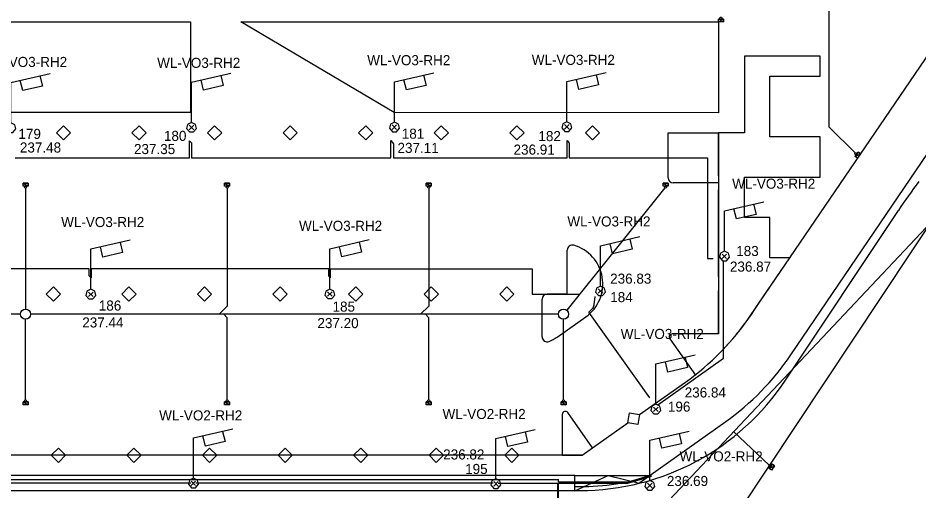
# Model space of a CAD drawing. Extents: x -264222 to -263592, y -1242345 to -1242048.
# Drawn here: x -263871.6 to -263782.2, y -1242301.5 to -1242254.6 of the extents above; entities that cross this region are included whole.
import ezdxf

# ---------------------------------------------------------------- set-up
doc = ezdxf.new("R2010")
doc.units = 0
for name, color, linetype in [('BOD_CISLO', 7, 'Continuous'), ('BOD_SYMBOL', 7, 'Continuous'), ('BOD_VYSKA', 7, 'Continuous'), ('KFA_2D_SITUACIA_DSP', 7, 'Continuous'), ('KFA_SO_62-1_VO_LAMPY_MERANE', 7, 'Continuous'), ('KFA_SO_62-1_VO_POPIS_LAMP_PROJEKT', 7, 'Continuous'), ('KFA_SO_62-1_VO_TRASA_KABLOV_PROJEKT', 7, 'Continuous')]:
    doc.layers.add(name, color=color, linetype=linetype)

msp = doc.modelspace()

# ---------------------------------------------------------------- linework, layer by layer
at = {"layer": 'BOD_SYMBOL'}
for p, q in [((-263817.336, -1242265.613), (-263816.894, -1242265.171)), ((-263816.894, -1242265.613), (-263817.336, -1242265.171)), ((-263854.587, -1242265.676), (-263854.145, -1242265.234)), ((-263854.145, -1242265.676), (-263854.587, -1242265.234)), ((-263834.447, -1242265.648), (-263834.005, -1242265.206)), ((-263834.005, -1242265.648), (-263834.447, -1242265.206)), ((-263801.697, -1242278.454), (-263801.255, -1242278.012)), ((-263801.255, -1242278.454), (-263801.697, -1242278.012)), ((-263864.574, -1242282.234), (-263864.132, -1242281.792)), ((-263864.132, -1242282.234), (-263864.574, -1242281.792)), ((-263840.849, -1242282.207), (-263840.407, -1242281.765)), ((-263840.407, -1242282.207), (-263840.849, -1242281.765)), ((-263813.995, -1242281.912), (-263813.553, -1242281.47)), ((-263813.553, -1242281.912), (-263813.995, -1242281.47)), ((-263808.507, -1242293.645), (-263808.065, -1242293.203)), ((-263808.065, -1242293.645), (-263808.507, -1242293.203)), ((-263854.391, -1242300.987), (-263853.949, -1242300.545)), ((-263853.949, -1242300.987), (-263854.391, -1242300.545)), ((-263824.373, -1242301.038), (-263823.931, -1242300.596)), ((-263823.931, -1242301.038), (-263824.373, -1242300.596)), ((-263809.101, -1242301.204), (-263808.659, -1242300.762)), ((-263808.659, -1242301.204), (-263809.101, -1242300.762))]:
    msp.add_line(p, q, dxfattribs=at)
at = {"layer": 'KFA_2D_SITUACIA_DSP'}
for p, q in [((-263822.88, -1242337.914), (-263734.49, -1242204.937)), ((-263794.898, -1242288.032), (-263742.736, -1242211.145)), ((-263798.899, -1242284.125), (-263751.864, -1242215.081)), ((-263791.063, -1242265.427), (-263791.063, -1242253.362)), ((-263802.071, -1242254.697), (-263801.571, -1242254.697)), ((-263802.071, -1242254.987), (-263802.071, -1242254.697)), ((-263802.071, -1242254.697), (-263801.571, -1242254.987)), ((-263802.071, -1242254.697), (-263801.571, -1242254.987)), ((-263801.571, -1242254.697), (-263802.071, -1242254.697)), ((-263801.571, -1242254.987), (-263802.071, -1242254.987)), ((-263801.571, -1242254.697), (-263801.571, -1242254.987)), ((-263801.571, -1242254.987), (-263801.571, -1242254.697)), ((-263807.068, -1242270.447), (-263807.068, -1242265.987)), ((-263807.068, -1242265.987), (-263802.068, -1242265.987)), ((-263802.068, -1242270.24), (-263802.068, -1242265.987)), ((-263788.502, -1242267.989), (-263791.063, -1242265.427)), ((-263788.491, -1242268.322), (-263788.207, -1242267.91)), ((-263788.207, -1242267.91), (-263788.491, -1242268.322)), ((-263788.491, -1242268.322), (-263787.968, -1242268.075)), ((-263788.491, -1242268.322), (-263787.968, -1242268.075)), ((-263788.252, -1242268.487), (-263788.491, -1242268.322)), ((-263787.968, -1242268.075), (-263788.252, -1242268.487)), ((-263788.207, -1242267.91), (-263787.968, -1242268.075)), ((-263787.968, -1242268.075), (-263788.207, -1242267.91)), ((-263871.074, -1242270.983), (-263870.574, -1242270.983)), ((-263871.074, -1242271.273), (-263871.074, -1242270.983)), ((-263871.074, -1242270.983), (-263870.574, -1242271.273)), ((-263871.074, -1242270.983), (-263870.574, -1242271.273)), ((-263870.574, -1242270.983), (-263871.074, -1242270.983)), ((-263870.574, -1242271.273), (-263871.074, -1242271.273)), ((-263870.574, -1242270.983), (-263870.574, -1242271.273)), ((-263870.574, -1242271.273), (-263870.574, -1242270.983)), ((-263851.074, -1242270.983), (-263850.574, -1242270.983)), ((-263851.074, -1242271.273), (-263851.074, -1242270.983)), ((-263851.074, -1242270.983), (-263850.574, -1242271.273)), ((-263851.074, -1242270.983), (-263850.574, -1242271.273)), ((-263850.574, -1242270.983), (-263851.074, -1242270.983)), ((-263850.574, -1242271.273), (-263851.074, -1242271.273)), ((-263850.574, -1242270.983), (-263850.574, -1242271.273)), ((-263850.574, -1242271.273), (-263850.574, -1242270.983)), ((-263831.074, -1242270.983), (-263830.574, -1242270.983)), ((-263831.074, -1242271.273), (-263831.074, -1242270.983)), ((-263831.074, -1242270.983), (-263830.574, -1242271.273)), ((-263831.074, -1242270.983), (-263830.574, -1242271.273)), ((-263830.574, -1242270.983), (-263831.074, -1242270.983)), ((-263830.574, -1242271.273), (-263831.074, -1242271.273)), ((-263830.574, -1242270.983), (-263830.574, -1242271.273)), ((-263830.574, -1242271.273), (-263830.574, -1242270.983)), ((-263807.568, -1242270.982), (-263807.068, -1242270.982)), ((-263807.568, -1242271.272), (-263807.568, -1242270.982)), ((-263807.568, -1242270.982), (-263807.068, -1242271.272)), ((-263807.568, -1242270.982), (-263807.068, -1242271.272)), ((-263807.068, -1242270.982), (-263807.568, -1242270.982)), ((-263807.068, -1242271.272), (-263807.568, -1242271.272)), ((-263807.068, -1242270.982), (-263807.068, -1242271.272)), ((-263807.068, -1242271.272), (-263807.068, -1242270.982)), ((-263802.068, -1242270.947), (-263806.568, -1242270.947)), ((-263870.824, -1242271.473), (-263870.824, -1242283.482)), ((-263850.824, -1242271.473), (-263850.824, -1242283.187)), ((-263830.824, -1242271.473), (-263830.824, -1242283.187)), ((-263807.38, -1242271.45), (-263817.128, -1242283.593)), ((-263802.068, -1242280.24), (-263802.068, -1242271.654)), ((-263795.416, -1242290.541), (-263784.214, -1242273.68)), ((-263780.353, -1242274.236), (-263808.248, -1242303.783)), ((-263817.068, -1242281.982), (-263817.068, -1242277.62)), ((-263817.068, -1242281.982), (-263819.068, -1242281.982)), ((-263802.068, -1242285.947), (-263802.068, -1242281.654)), ((-263819.568, -1242286.231), (-263819.568, -1242282.482)), ((-263850.824, -1242283.187), (-263851.619, -1242283.982)), ((-263830.824, -1242283.187), (-263831.619, -1242283.982)), ((-263871.324, -1242283.982), (-263903.413, -1242283.982)), ((-263870.824, -1242292.492), (-263870.824, -1242284.482)), ((-263817.941, -1242283.982), (-263870.324, -1242283.982)), ((-263817.941, -1242283.982), (-263870.324, -1242283.982)), ((-263850.824, -1242284.343), (-263851.149, -1242283.982)), ((-263850.824, -1242292.492), (-263850.824, -1242284.343)), ((-263830.824, -1242284.343), (-263831.149, -1242283.982)), ((-263830.824, -1242292.492), (-263830.824, -1242284.343)), ((-263818.06, -1242286.248), (-263815.232, -1242284.248)), ((-263817.441, -1242292.492), (-263817.441, -1242284.482)), ((-263809.895, -1242293.947), (-263805.344, -1242290.728)), ((-263871.074, -1242292.693), (-263870.574, -1242292.693)), ((-263871.074, -1242292.983), (-263871.074, -1242292.693)), ((-263871.074, -1242292.693), (-263870.574, -1242292.983)), ((-263871.074, -1242292.693), (-263870.574, -1242292.983)), ((-263870.574, -1242292.693), (-263871.074, -1242292.693)), ((-263870.574, -1242292.693), (-263870.574, -1242292.983)), ((-263870.574, -1242292.983), (-263870.574, -1242292.693)), ((-263851.074, -1242292.693), (-263850.574, -1242292.693)), ((-263851.074, -1242292.983), (-263851.074, -1242292.693)), ((-263851.074, -1242292.693), (-263850.574, -1242292.983)), ((-263851.074, -1242292.693), (-263850.574, -1242292.983)), ((-263850.574, -1242292.693), (-263851.074, -1242292.693)), ((-263850.574, -1242292.693), (-263850.574, -1242292.983)), ((-263850.574, -1242292.983), (-263850.574, -1242292.693)), ((-263831.074, -1242292.693), (-263830.574, -1242292.693)), ((-263831.074, -1242292.983), (-263831.074, -1242292.693)), ((-263831.074, -1242292.693), (-263830.574, -1242292.983)), ((-263831.074, -1242292.693), (-263830.574, -1242292.983)), ((-263830.574, -1242292.693), (-263831.074, -1242292.693)), ((-263830.824, -1242292.693), (-263830.824, -1242292.692)), ((-263830.574, -1242292.693), (-263830.574, -1242292.983)), ((-263830.574, -1242292.983), (-263830.574, -1242292.693)), ((-263817.691, -1242292.692), (-263817.191, -1242292.692)), ((-263817.691, -1242292.982), (-263817.691, -1242292.692)), ((-263817.691, -1242292.692), (-263817.191, -1242292.982)), ((-263817.691, -1242292.692), (-263817.191, -1242292.982)), ((-263817.191, -1242292.692), (-263817.691, -1242292.692)), ((-263817.191, -1242292.692), (-263817.191, -1242292.982)), ((-263817.191, -1242292.982), (-263817.191, -1242292.692)), ((-263870.574, -1242292.983), (-263871.074, -1242292.983)), ((-263850.574, -1242292.983), (-263851.074, -1242292.983)), ((-263830.574, -1242292.983), (-263831.074, -1242292.983)), ((-263817.191, -1242292.982), (-263817.691, -1242292.982)), ((-263809.875, -1242300.669), (-263801.342, -1242294.634)), ((-263814.555, -1242297.242), (-263811.05, -1242294.763)), ((-263797.048, -1242298.952), (-263800.558, -1242295.638)), ((-263815.601, -1242297.982), (-263917.08, -1242297.982)), ((-263797.029, -1242299.286), (-263796.75, -1242298.871)), ((-263796.75, -1242298.871), (-263797.029, -1242299.286)), ((-263797.029, -1242299.286), (-263796.51, -1242299.032)), ((-263797.029, -1242299.286), (-263796.51, -1242299.032)), ((-263796.51, -1242299.032), (-263796.788, -1242299.448)), ((-263796.75, -1242298.871), (-263796.51, -1242299.032)), ((-263796.51, -1242299.032), (-263796.75, -1242298.871)), ((-263816.308, -1242299.982), (-263918.049, -1242299.982)), ((-263816.308, -1242301.482), (-263816.308, -1242299.982)), ((-263816.308, -1242299.982), (-263808.904, -1242299.982)), ((-263796.788, -1242299.448), (-263797.029, -1242299.286)), ((-263809.906, -1242300.757), (-263809.875, -1242300.669)), ((-263914.08, -1242301.482), (-263815.822, -1242301.482))]:
    msp.add_line(p, q, dxfattribs=at)
for points in [[(-263854.468, -1242263.985), (-263917.08, -1242263.982), (-263901.868, -1242254.982), (-263854.468, -1242254.985), (-263854.468, -1242263.985)], [(-263798.064, -1242282.882), (-263794.987, -1242278.383), (-263796.968, -1242278.382), (-263796.968, -1242274.382), (-263799.468, -1242274.382), (-263799.468, -1242270.382), (-263791.968, -1242270.382), (-263791.968, -1242266.382), (-263796.968, -1242266.382), (-263796.968, -1242260.382), (-263791.968, -1242260.382), (-263791.968, -1242258.382), (-263799.468, -1242258.382), (-263799.468, -1242265.987), (-263802.068, -1242265.987)], [(-263802.068, -1242265.987), (-263802.068, -1242270.24), (-263802.068, -1242270.947), (-263802.068, -1242271.654), (-263802.068, -1242273.447), (-263802.068, -1242275.947), (-263802.068, -1242278.447), (-263802.068, -1242280.24), (-263802.068, -1242280.24), (-263802.068, -1242281.654), (-263802.068, -1242283.447), (-263802.068, -1242285.947), (-263806.656, -1242285.943)], [(-263806.901, -1242286.416), (-263804.349, -1242290.024), (-263802.552, -1242288.44)], [(-263817.568, -1242293.926), (-263817.568, -1242297.982), (-263815.601, -1242297.982), (-263814.555, -1242297.242), (-263817.023, -1242293.753)], [(-263816.327, -1242301.51), (-263813.002, -1242299.982), (-263809.906, -1242300.757)]]:
    msp.add_lwpolyline(points, dxfattribs=at)
for points in [[(-263802.068, -1242263.988), (-263834.256, -1242263.984), (-263849.468, -1242254.985), (-263802.068, -1242254.987)], [(-263867.068, -1242265.279), (-263866.361, -1242265.986), (-263867.068, -1242266.693), (-263867.775, -1242265.986)], [(-263859.568, -1242265.279), (-263858.861, -1242265.986), (-263859.568, -1242266.693), (-263860.275, -1242265.986)], [(-263852.068, -1242265.279), (-263851.361, -1242265.986), (-263852.068, -1242266.693), (-263852.775, -1242265.986)], [(-263844.568, -1242265.279), (-263843.861, -1242265.986), (-263844.568, -1242266.693), (-263845.275, -1242265.986)], [(-263837.068, -1242265.279), (-263836.361, -1242265.986), (-263837.068, -1242266.693), (-263837.775, -1242265.986)], [(-263829.568, -1242265.279), (-263828.861, -1242265.986), (-263829.568, -1242266.693), (-263830.275, -1242265.986)], [(-263822.068, -1242265.279), (-263821.361, -1242265.986), (-263822.068, -1242266.694), (-263822.775, -1242265.986)], [(-263814.568, -1242265.279), (-263813.861, -1242265.986), (-263814.568, -1242266.693), (-263815.275, -1242265.986)], [(-263868.068, -1242281.275), (-263867.361, -1242281.982), (-263868.068, -1242282.689), (-263868.775, -1242281.982)], [(-263860.568, -1242281.275), (-263859.861, -1242281.982), (-263860.568, -1242282.689), (-263861.275, -1242281.982)], [(-263853.068, -1242281.275), (-263852.361, -1242281.982), (-263853.068, -1242282.689), (-263853.775, -1242281.982)], [(-263845.568, -1242281.275), (-263844.861, -1242281.982), (-263845.568, -1242282.689), (-263846.275, -1242281.982)], [(-263838.068, -1242281.275), (-263837.361, -1242281.982), (-263838.068, -1242282.689), (-263838.775, -1242281.982)], [(-263830.568, -1242281.275), (-263829.861, -1242281.982), (-263830.568, -1242282.689), (-263831.275, -1242281.982)], [(-263823.068, -1242281.275), (-263822.361, -1242281.982), (-263823.068, -1242282.689), (-263823.775, -1242281.982)], [(-263810.881, -1242293.778), (-263809.895, -1242293.947), (-263810.064, -1242294.932), (-263811.05, -1242294.763)], [(-263867.568, -1242297.275), (-263866.861, -1242297.982), (-263867.568, -1242298.689), (-263868.275, -1242297.982)], [(-263860.068, -1242297.275), (-263859.361, -1242297.982), (-263860.068, -1242298.689), (-263860.775, -1242297.982)], [(-263852.568, -1242297.275), (-263851.861, -1242297.982), (-263852.568, -1242298.689), (-263853.275, -1242297.982)], [(-263845.068, -1242297.275), (-263844.361, -1242297.982), (-263845.068, -1242298.689), (-263845.775, -1242297.982)], [(-263837.568, -1242297.275), (-263836.861, -1242297.982), (-263837.568, -1242298.689), (-263838.275, -1242297.982)], [(-263830.068, -1242297.275), (-263829.361, -1242297.982), (-263830.068, -1242298.689), (-263830.775, -1242297.982)], [(-263822.568, -1242297.275), (-263821.861, -1242297.982), (-263822.568, -1242298.689), (-263823.275, -1242297.982)]]:
    msp.add_lwpolyline(points, close=True, dxfattribs=at)
for centre, radius in [((-263801.821, -1242254.597), 0.1), ((-263788.431, -1242268.059), 0.1), ((-263870.824, -1242271.373), 0.1), ((-263850.824, -1242271.373), 0.1), ((-263830.824, -1242271.373), 0.1), ((-263807.318, -1242271.372), 0.1), ((-263870.824, -1242283.982), 0.5), ((-263817.441, -1242283.982), 0.5), ((-263870.824, -1242292.592), 0.1), ((-263850.824, -1242292.592), 0.1), ((-263830.824, -1242292.592), 0.1), ((-263817.441, -1242292.592), 0.1), ((-263796.975, -1242299.02), 0.1)]:
    msp.add_circle(centre, radius, dxfattribs=at)
for centre, radius, start, end in [((-263806.568, -1242270.447), 0.5, 180, 270), ((-263742.568, -1242301.35), 50, 142.36875, 146.39918), ((-263816.568, -1242277.62), 0.5, 73.84458, 180), ((-263817.542, -1242280.982), 4, 305.27024, 73.84458), ((-263819.068, -1242282.482), 0.5, 90, 180), ((-263821.806, -1242268.304), 27.86, 313.71918, 328.45017), ((-263820.069, -1242269.909), 25.5, 305.27024, 326.11647), ((-263819.068, -1242286.231), 0.5, 180, 291.83316), ((-263820.369, -1242282.982), 4, 291.83316, 305.27024), ((-263806.656, -1242286.243), 0.3, 89.94357, 215.27024), ((-263816.067, -1242273.815), 25.5, 305.27024, 326.11647), ((-263815.822, -1242276.982), 24.5, 270, 326.39918), ((-263817.268, -1242293.926), 0.3, 35.27024, 180), ((-263815.836, -1242276.967), 24.119, 268.87866, 286.17976)]:
    msp.add_arc(centre, radius, start, end, dxfattribs=at)
at = {"layer": 'KFA_SO_62-1_VO_LAMPY_MERANE'}
for p, q in [((-263854.416, -1242265.455), (-263854.316, -1242265.455)), ((-263854.366, -1242265.455), (-263854.366, -1242265.455)), ((-263834.276, -1242265.427), (-263834.176, -1242265.427)), ((-263834.226, -1242265.427), (-263834.226, -1242265.427)), ((-263817.165, -1242265.392), (-263817.065, -1242265.392)), ((-263817.115, -1242265.392), (-263817.115, -1242265.392)), ((-263801.526, -1242278.233), (-263801.426, -1242278.233)), ((-263801.476, -1242278.233), (-263801.476, -1242278.233)), ((-263864.403, -1242282.013), (-263864.303, -1242282.013)), ((-263864.353, -1242282.013), (-263864.353, -1242282.013)), ((-263840.678, -1242281.986), (-263840.578, -1242281.986)), ((-263840.628, -1242281.986), (-263840.628, -1242281.986)), ((-263813.824, -1242281.691), (-263813.724, -1242281.691)), ((-263813.774, -1242281.691), (-263813.774, -1242281.691)), ((-263808.336, -1242293.424), (-263808.236, -1242293.424)), ((-263808.286, -1242293.424), (-263808.286, -1242293.424)), ((-263854.22, -1242300.766), (-263854.12, -1242300.766)), ((-263854.17, -1242300.766), (-263854.17, -1242300.766)), ((-263824.202, -1242300.817), (-263824.102, -1242300.817)), ((-263824.152, -1242300.817), (-263824.152, -1242300.817)), ((-263808.93, -1242300.983), (-263808.83, -1242300.983)), ((-263808.88, -1242300.983), (-263808.88, -1242300.983))]:
    msp.add_line(p, q, dxfattribs=at)
for points in [[(-263872.3, -1242264.999), (-263872.7, -1242265.199), (-263872.8, -1242265.599), (-263872.5, -1242265.949), (-263872.1, -1242265.949), (-263871.8, -1242265.599), (-263871.9, -1242265.199), (-263872.3, -1242264.999), (-263872.3, -1242260.999), (-263868.4, -1242260.099)], [(-263869.4, -1242260.349), (-263869.15, -1242261.349), (-263871.1, -1242261.799), (-263871.35, -1242260.799)], [(-263854.366, -1242264.955), (-263854.766, -1242265.155), (-263854.866, -1242265.555), (-263854.566, -1242265.905), (-263854.166, -1242265.905), (-263853.866, -1242265.555), (-263853.966, -1242265.155), (-263854.366, -1242264.955), (-263854.366, -1242260.955), (-263850.466, -1242260.055)], [(-263851.466, -1242260.305), (-263851.216, -1242261.305), (-263853.166, -1242261.755), (-263853.416, -1242260.755)], [(-263834.226, -1242264.927), (-263834.626, -1242265.127), (-263834.726, -1242265.527), (-263834.426, -1242265.877), (-263834.026, -1242265.877), (-263833.726, -1242265.527), (-263833.826, -1242265.127), (-263834.226, -1242264.927), (-263834.226, -1242260.927), (-263830.326, -1242260.027)], [(-263831.326, -1242260.277), (-263831.076, -1242261.277), (-263833.026, -1242261.727), (-263833.276, -1242260.727)], [(-263817.115, -1242264.892), (-263817.515, -1242265.092), (-263817.615, -1242265.492), (-263817.315, -1242265.842), (-263816.915, -1242265.842), (-263816.615, -1242265.492), (-263816.715, -1242265.092), (-263817.115, -1242264.892), (-263817.115, -1242260.892), (-263813.215, -1242259.992)], [(-263814.215, -1242260.242), (-263813.965, -1242261.242), (-263815.915, -1242261.692), (-263816.165, -1242260.692)], [(-263801.476, -1242277.733), (-263801.876, -1242277.933), (-263801.976, -1242278.333), (-263801.676, -1242278.683), (-263801.276, -1242278.683), (-263800.976, -1242278.333), (-263801.076, -1242277.933), (-263801.476, -1242277.733), (-263801.476, -1242273.733), (-263797.576, -1242272.833)], [(-263798.576, -1242273.083), (-263798.326, -1242274.083), (-263800.276, -1242274.533), (-263800.526, -1242273.533)], [(-263864.353, -1242281.513), (-263864.753, -1242281.713), (-263864.853, -1242282.113), (-263864.553, -1242282.463), (-263864.153, -1242282.463), (-263863.853, -1242282.113), (-263863.953, -1242281.713), (-263864.353, -1242281.513), (-263864.353, -1242277.513), (-263860.453, -1242276.613)], [(-263840.628, -1242281.486), (-263841.028, -1242281.686), (-263841.128, -1242282.086), (-263840.828, -1242282.436), (-263840.428, -1242282.436), (-263840.128, -1242282.086), (-263840.228, -1242281.686), (-263840.628, -1242281.486), (-263840.628, -1242277.486), (-263836.728, -1242276.586)], [(-263813.774, -1242281.191), (-263814.174, -1242281.391), (-263814.274, -1242281.791), (-263813.974, -1242282.141), (-263813.574, -1242282.141), (-263813.274, -1242281.791), (-263813.374, -1242281.391), (-263813.774, -1242281.191), (-263813.774, -1242277.191), (-263809.874, -1242276.291)], [(-263810.874, -1242276.541), (-263810.624, -1242277.541), (-263812.574, -1242277.991), (-263812.824, -1242276.991)], [(-263861.453, -1242276.863), (-263861.203, -1242277.863), (-263863.153, -1242278.313), (-263863.403, -1242277.313)], [(-263837.728, -1242276.836), (-263837.478, -1242277.836), (-263839.428, -1242278.286), (-263839.678, -1242277.286)], [(-263808.286, -1242292.924), (-263808.686, -1242293.124), (-263808.786, -1242293.524), (-263808.486, -1242293.874), (-263808.086, -1242293.874), (-263807.786, -1242293.524), (-263807.886, -1242293.124), (-263808.286, -1242292.924), (-263808.286, -1242288.924), (-263804.386, -1242288.024)], [(-263805.386, -1242288.274), (-263805.136, -1242289.274), (-263807.086, -1242289.724), (-263807.336, -1242288.724)], [(-263854.17, -1242300.266), (-263854.57, -1242300.466), (-263854.67, -1242300.866), (-263854.37, -1242301.216), (-263853.97, -1242301.216), (-263853.67, -1242300.866), (-263853.77, -1242300.466), (-263854.17, -1242300.266), (-263854.17, -1242296.266), (-263850.27, -1242295.366)], [(-263824.152, -1242300.317), (-263824.552, -1242300.517), (-263824.652, -1242300.917), (-263824.352, -1242301.267), (-263823.952, -1242301.267), (-263823.652, -1242300.917), (-263823.752, -1242300.517), (-263824.152, -1242300.317), (-263824.152, -1242296.317), (-263820.252, -1242295.417)], [(-263808.88, -1242300.483), (-263809.28, -1242300.683), (-263809.38, -1242301.083), (-263809.08, -1242301.433), (-263808.68, -1242301.433), (-263808.38, -1242301.083), (-263808.48, -1242300.683), (-263808.88, -1242300.483), (-263808.88, -1242296.483), (-263804.98, -1242295.583)], [(-263851.27, -1242295.616), (-263851.02, -1242296.616), (-263852.97, -1242297.066), (-263853.22, -1242296.066)], [(-263821.252, -1242295.667), (-263821.002, -1242296.667), (-263822.952, -1242297.117), (-263823.202, -1242296.117)], [(-263805.98, -1242295.833), (-263805.73, -1242296.833), (-263807.68, -1242297.283), (-263807.93, -1242296.283)]]:
    msp.add_lwpolyline(points, dxfattribs=at)
at = {"layer": 'KFA_SO_62-1_VO_TRASA_KABLOV_PROJEKT'}
for p, q in [((-263854.568, -1242268.463), (-263854.568, -1242266.768)), ((-263854.568, -1242266.768), (-263854.357, -1242266.976)), ((-263854.357, -1242266.976), (-263854.357, -1242268.463)), ((-263834.568, -1242268.463), (-263834.568, -1242266.764)), ((-263834.568, -1242266.764), (-263834.32, -1242267.08)), ((-263817.068, -1242268.463), (-263817.068, -1242266.765)), ((-263817.068, -1242266.765), (-263816.865, -1242267.008)), ((-263834.32, -1242267.08), (-263834.32, -1242268.463)), ((-263816.865, -1242267.008), (-263816.865, -1242268.463)), ((-263871.858, -1242268.463), (-263854.568, -1242268.463)), ((-263854.357, -1242268.463), (-263834.568, -1242268.463)), ((-263834.32, -1242268.463), (-263817.068, -1242268.463)), ((-263816.865, -1242268.463), (-263803.15, -1242268.463)), ((-263803.15, -1242268.463), (-263803.15, -1242278.447)), ((-263803.15, -1242278.447), (-263802.589, -1242278.447)), ((-263864.522, -1242279.482), (-263888.068, -1242279.482)), ((-263864.522, -1242280.178), (-263864.522, -1242279.482)), ((-263840.736, -1242279.482), (-263864.31, -1242279.482)), ((-263864.31, -1242279.482), (-263864.31, -1242280.377)), ((-263840.736, -1242280.216), (-263840.736, -1242279.482)), ((-263840.571, -1242280.373), (-263840.571, -1242279.482)), ((-263840.571, -1242279.482), (-263820.568, -1242279.482)), ((-263820.568, -1242279.482), (-263820.568, -1242281.982)), ((-263801.558, -1242288.362), (-263801.558, -1242278.697)), ((-263864.31, -1242280.377), (-263864.522, -1242280.178)), ((-263840.571, -1242280.373), (-263840.736, -1242280.216)), ((-263820.568, -1242281.982), (-263815.925, -1242281.982)), ((-263814.51, -1242283.35), (-263814.4, -1242283.05)), ((-263814.4, -1242283.05), (-263814.313, -1242282.232)), ((-263814.94, -1242283.77), (-263814.71, -1242283.56)), ((-263808.865, -1242292.299), (-263814.94, -1242283.77)), ((-263814.71, -1242283.56), (-263814.51, -1242283.35)), ((-263808.08, -1242292.976), (-263801.558, -1242288.362)), ((-263811.045, -1242300.75), (-263808.72, -1242300.04)), ((-263808.896, -1242300.019), (-263811.043, -1242300.664)), ((-263808.72, -1242300.04), (-263808.896, -1242300.019)), ((-263918.795, -1242300.4), (-263817.945, -1242300.4)), ((-263854.424, -1242300.744), (-263883.924, -1242300.744)), ((-263824.424, -1242300.744), (-263853.924, -1242300.744)), ((-263823.924, -1242300.744), (-263818.045, -1242300.744)), ((-263818.045, -1242300.744), (-263818.045, -1242307.43)), ((-263817.945, -1242300.664), (-263817.945, -1242300.4)), ((-263811.043, -1242300.664), (-263817.945, -1242300.664)), ((-263817.945, -1242307.399), (-263817.945, -1242300.75)), ((-263817.945, -1242300.75), (-263811.045, -1242300.75))]:
    msp.add_line(p, q, dxfattribs=at)

# ---------------------------------------------------------------- texts
at = {"layer": 'BOD_CISLO'}
for s, p in [('179', (-263871.537, -1242266.592)), ('180', (-263857.096, -1242266.791)), ('181', (-263833.492, -1242266.572)), ('182', (-263819.933, -1242266.813)), ('183', (-263800.302, -1242278.212)), ('184', (-263812.805, -1242282.788)), ('186', (-263863.561, -1242283.624)), ('185', (-263840.364, -1242283.733)), ('196', (-263807.083, -1242293.656)), ('195', (-263827.204, -1242299.84))]:
    msp.add_text(s, height=1, dxfattribs=at).set_placement(p)
at = {"layer": 'BOD_VYSKA'}
for s, p in [('237.48', (-263871.392, -1242267.943)), ('237.11', (-263833.918, -1242267.983)), ('237.35', (-263860.067, -1242268.099)), ('236.91', (-263822.402, -1242268.153)), ('236.87', (-263800.926, -1242279.76)), ('236.83', (-263812.815, -1242280.957)), ('237.44', (-263865.2, -1242285.303)), ('237.20', (-263841.864, -1242285.364)), ('236.84', (-263805.413, -1242292.249)), ('236.82', (-263829.385, -1242298.402)), ('236.69', (-263807.186, -1242301.033))]:
    msp.add_text(s, height=1, dxfattribs=at).set_placement(p)
at = {"layer": 'KFA_SO_62-1_VO_POPIS_LAMP_PROJEKT'}
for s, p in [('WL-VO3-RH2', (-263874.95, -1242259.454)), ('WL-VO3-RH2', (-263857.768, -1242259.544)), ('WL-VO3-RH2', (-263836.922, -1242259.28)), ('WL-VO3-RH2', (-263820.594, -1242259.249)), ('WL-VO3-RH2', (-263800.705, -1242271.534)), ('WL-VO3-RH2', (-263867.297, -1242275.338)), ('WL-VO3-RH2', (-263843.691, -1242275.714)), ('WL-VO3-RH2', (-263817.06, -1242275.28)), ('WL-VO3-RH2', (-263811.769, -1242286.445)), ('WL-VO2-RH2', (-263857.569, -1242294.524)), ('WL-VO2-RH2', (-263829.446, -1242294.386)), ('WL-VO2-RH2', (-263805.926, -1242298.591))]:
    msp.add_text(s, height=1, dxfattribs=at).set_placement(p)

doc.saveas('drawing.dxf')
